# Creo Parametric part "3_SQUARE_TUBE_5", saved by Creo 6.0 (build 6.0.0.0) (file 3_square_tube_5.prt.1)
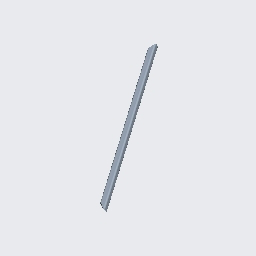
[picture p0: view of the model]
Units: Custom; MM, KILOGRAM, SECS
Materials in the file: STEEL

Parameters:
  BUW_NAME = "SQUARE TUBE"
  BUW_TYPE = "DIN EN 10219"
  BUW_SIZE = "25x25x3.0"
  BUW_LENGTH_STR = "705"
  PTC_MATERIAL_NAME = "STEEL"
  BUW_PROFIL_TYPE = "square_tube"
  BUW_PROFILE_PATH = "parts//profiles/steel_beams_mm/"
  BUW_PROFILE_NAME_LANG = "SQUARE TUBE"
  BUW_TAB_SEL_INFO = "-2 TYPE DIN_EN_10219-1997 SIZE_DINEN_10219 25x25x3.0"
  NAMING = "SQUARE TUBE"
  DESIGNATION = "DIN EN 10219 25x25x3.0 x 705"
  PROFIL_RASTER_POS = "X_0"
  BUW_OBJECT_ROLE = "PROFIL_SYSTEM_BORE_END_POINTS"
  PRO_UNIT_SYS = "Custom"

Other parameters: BUW_LENGTH, LENGTH, BUW_LENGTH_Z_MIN_PARAM, D8, D93, D94, d26, d8, d93, d94, d98, D98, SHEAR_MODULUS, THERM_EXPANSION_REF_TEMPERATURE, STRUCTURAL_DAMPING_COEFFICIENT, STRESS_LIMIT_FOR_TENSION, STRESS_LIMIT_FOR_COMPRESSION, STRESS_LIMIT_FOR_SHEAR, EMISSIVITY

Created from: SQUARE_TUBE.PRT

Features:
  1. datum plane "YZ"
  2. datum plane "XZ"
  3. datum plane "XY"
  4. coordinate system
  5. coordinate system
  6. coordinate system
  7. coordinate system
  8. datum plane "DTM3"
  9. datum plane "DTM4"
  10. datum plane "DTM5"
  11. protrusion
  12. round
  13. round
  14. datum axis
  15. datum point "PNT0"
  16. datum point

Other named items: PROFIL_CUT_QUILT, PROFILE_LENGTH_DIM, CONTACT_SURF_3, CONTACT_SURF_2, CONTACT_SURF_1, CONTACT_SURF_0, E, START_SURFACE, END_SURFACE, SIDE_SURF_3, SIDE_SURF_0, SIDE_SURF_1, SIDE_SURF_2, EDGE_7_S, EDGE_7_E, EDGE_1_S, EDGE_1_E, EDGE_3_S, EDGE_3_E, EDGE_5_S, EDGE_5_E, EDGE_6_S, EDGE_4_S, EDGE_2_S, EDGE_0_S, EDGE_6_E, EDGE_4_E, EDGE_2_E, EDGE_0_E, CS0, CS_S, CS_E, CS3

Named dimensions: X_ROT_S, Y_ROT_S, Z_OFF_S, X_ROT_E, Y_ROT_E, Z_OFF_E, PC_L, BUW_LENGTH_Z_MIN, BUW_LENGTH_DIM

Layers: 00_PROFIL_DATUM, 00_PROFIL_DRW_HIDE, 00_PROFIL_END_CSYS, 00_PROFIL_GEOMETRY, 00_PROFIL_QUILT, 00_PROFIL_SIZE_NOTE

Surfaces: 16 plane, 12 cylinder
